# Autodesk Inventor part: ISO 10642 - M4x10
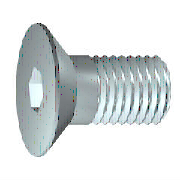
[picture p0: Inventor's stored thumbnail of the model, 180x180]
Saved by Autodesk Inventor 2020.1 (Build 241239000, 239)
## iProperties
Created: 2019-01
Part Number: ISO 10642 - M4x10
Material: Stahl, weich
Description: Senkschrauben mit Innensechskant
Document SubType Name: Modeling
Standard: ISO 10642
Designer: lutzd
Standards Organization: ISO
Language: de-DE
Size Designation: M4x10
Categories: <MemberInstance><Categories><Category DisplayName="Verbindungselemente" InternalName="e4da775c-781d-43d5-af7c-5136215cf5a6" Mnemonic="FSTN"><Category DisplayNam
Mass: 1.25621 g
Surface Area: 2.33196 cm^2
Volume: 0.160027 cm^3
Density: 7.85 g/cm^3
Appearance: Halbpoliert
IsCustomPart: 0
Author: lutzd
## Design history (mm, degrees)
node "WorkPoint1"
sketch "Skizze2"
  geometry: L1 (-2, -10)-(0, -10); L2 (-2, -2.3)-(-2, -10); L3 (-4, -0.3)-(-2, -2.3); L4 (-4, 0)-(-4, -0.3); L5 (0, 0)-(-4, 0); L6 (0, -10)-(0, 0); L7 (0, -10)-(0, 0); L8 (0, -12)-(0, 2) reference; L9 (0.8, 0)-(-4.8, 0) reference
  constraints: 14 end point, 3 vertical, 2 horizontal
  dimensions: "d3" = 4 distance of L5.start L4.start (= 0.5 x dk); "d5" = 2 distance of L1.start L1.end (= 0.5 x NND); "d7" = 10 distance of L1.end L5.start (= NLG); "ParC" = 0.3 distance of L4.start L3.start; "d22" = 0 distance between parallel lines of L8 L6; "d23" = 0 distance between parallel lines of L9 L5; "d43" = 45 deg angle of L6 L3 (= 0.5 x ang)
revolve "Drehung1" stored, may be unused: angle "d8" = 360 deg
node "MSC_A1"
node "MSC_PF1"
node "MSC_PT1"
body "Solid1"
node "Skizze1"
sketch "Skizze3"
  geometry: L1 (-1.25, 0.722)-(-1.25, -0.722); L2 (0, 1.443)-(-1.25, 0.722); L3 (1.25, 0.722)-(0, 1.443); L4 (1.25, -0.722)-(1.25, 0.722); L5 (0, -1.443)-(1.25, -0.722); L6 (-1.25, -0.722)-(0, -1.443); C1 r 1.25 at (0, 0); C2 r 2 at (0, 0) reference
  constraints: 12 end point, 6 tangent, 2 parallel, 2 vertical, 1 centre point, 1 concentric
  dimensions: "d11" = 2.5 diameter of C1 (= ParS); "d13" = 120 deg angle of L1 L2; "d15" = 120 deg angle of L6 L1
extrude "Extrusion1" cut sketch "Skizze3" distance "d16" = 1.8 (= ParT); taper "d17" = 0 deg
fillet "Rundung1" dims "d18" = 0.2 (= r)
chamfer "Fase1" distance "d19" = 0.35 (= 0.5 x PTC); stored, may be unused: angle "d20" = 45 deg, second distance "d39" = 0.35 (= 0.5 x PTC)
feature "Gewinde1" dims "d35" = 0, "b" = 6.3
other parameters: "NND" = 4 [user parameter; used in 2 equation terms], "PTC" = 0.7 [user parameter; used in 2 equation terms], "dk" = 8 [user parameter; used in 1 equation term], "ParK" = 2.3 [user parameter], "ParS" = 2.5 [user parameter; used in 1 equation term], "ParT" = 1.8 [user parameter; used in 1 equation term], "r" = 0.2 [user parameter; used in 1 equation term], "NLG" = 10 [user parameter; used in 1 equation term], "d0" = 45 deg (derived), "d2" = 3 (derived), "d4" = 1.5 (derived), "d6" = 8 (derived), "d9" = 0, "d10" = 2 (derived), "d12" = 120 deg (derived), "d14" = 120 deg (derived), "d37" = 0, "d38" = 0, "d40" = 0, "d41" = 0, "d42" = 0, "ang" = 90 deg [user parameter; used in 1 equation term], "THREADDIA" = 4 (= NND) [user parameter]
